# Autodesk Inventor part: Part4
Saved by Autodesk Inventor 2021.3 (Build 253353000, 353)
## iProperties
Created: 2022-09
Part Number: Part4
Material: Generic
Document SubType Name: Modeling
Designer: Administrator
Density: 1 g/cm^3
Appearance: Default
Author: Administrator
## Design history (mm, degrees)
feature "Set Screw"
feature "Strain Relief"
feature "Lead-1"
feature "Lead-2"
feature "Lead-2.1"
feature "Lead-1.1"
feature "Coax"
feature "Stem"
feature "Strain Relief Cap"
feature "Nylon Gripper (2)"
feature "Cap"
feature "Thumbscrew (1)"
feature "Thumbscrew (2)"
feature "Thumbscrew (3)"
feature "Niche-PCB"
feature "FJ-Plug Cover"
feature "FJ-Plug"
feature "FJ-Plug1.1"
feature "FJ-Plug1.2"
feature "FJ-Plug1.3"
feature "Fj-Plug1.4"
feature "Canopy"
feature "FJ-Port"
feature "FJ-Port1.1"
feature "Spacer"
feature "Universal Mount"
feature "FJ-Port Cover"
feature "Diffuser"
body "Solid1"
body "Solid2"
body "Solid3"
body "Solid4"
body "Solid5"
body "Solid6"
body "Solid7"
body "Solid8"
body "Solid9"
body "Solid10"
body "Solid11"
body "Solid12"
body "Solid13"
body "Solid14"
body "Solid15"
body "Solid16"
body "Solid17"
body "Solid18"
body "Solid19"
body "Solid20"
body "Solid21"
body "Solid22"
body "Solid23"
body "Solid24"
body "Solid25"
body "Solid26"
body "Solid27"
body "Solid28"
